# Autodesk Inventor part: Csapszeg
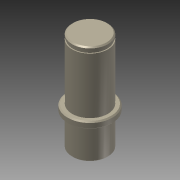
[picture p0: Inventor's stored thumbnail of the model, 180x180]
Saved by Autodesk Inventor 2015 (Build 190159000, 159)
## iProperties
Created: 2013-02
Part Number: Csapszeg
Material: Generic
Document SubType Name: Modeling
Designer: Marci
Density: 1 g/cm^3
Appearance: Light Beige
Author: Marci
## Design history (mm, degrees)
sketch "Sketch1"
  geometry: C1 r 8 at (0, 0); 1 further point
  constraints: 1 centre point, 1 coincident
  dimensions: "d0" = 16 diameter of C1
extrude "Extrusion1" new body sketch "Sketch1" distance "d1" = 14; taper "d2" = 0 deg
sketch "Sketch2"
  geometry: C1 r 8 at (0, 0) reference; C2 r 10 at (0, 0)
  constraints: 1 centre point, 1 coincident
  dimensions: "d3" = 20 diameter of C2
extrude "Extrusion2" join sketch "Sketch2" distance "d4" = 3; taper "d5" = 0 deg
sketch "Sketch3"
  geometry: C1 r 10 at (0, 0) reference; C2 r 8 at (0, 0)
  constraints: 1 centre point, 1 coincident
  dimensions: "d6" = 16 diameter of C2
extrude "Extrusion3" join sketch "Sketch3" distance "d7" = 27.5; taper "d8" = 0 deg
sketch "Sketch4"
  geometry: C1 r 8 at (0, 0) reference; C2 r 4 at (0, 0)
  constraints: 1 centre point, 1 coincident
  dimensions: "d9" = 8 diameter of C2
extrude "Extrusion4" cut sketch "Sketch4" distance "d10" = 20; taper "d11" = 0 deg
thread "Thread1" dims "d12" = 10, "d13" = 0
sketch "Sketch5"
  geometry: L1 (-8, 44.5)-(8, 44.5) reference; L2 (-8, 17)-(8, 17) reference; L3 (-8, 44.5)-(8, 44.5) reference; L4 (7.6, 42)-(7.6, 43); L5 (7.6, 43)-(9.849, 43); L6 (9.849, 43)-(9.849, 42); L7 (9.849, 42)-(7.6, 42); L8 (0, -8.9)-(0, 53.4) reference; 2 further points
  constraints: 8 end point
revolve "Revolution1" sketch "Sketch5" stored, may be unused: angle "d17" = 90 deg
chamfer "Chamfer1" distance "d18" = 0.5; stored, may be unused: second distance "d19" = 2, angle "d20" = 45 deg
chamfer "Chamfer2" distance "d21" = 0.5; stored, may be unused: second distance "d22" = 2, angle "d23" = 45 deg
chamfer "Chamfer3" distance "d24" = 0.5; stored, may be unused: second distance "d25" = 2, angle "d26" = 45 deg
chamfer "Chamfer4" distance "d27" = 0.5; stored, may be unused: second distance "d28" = 2, angle "d29" = 45 deg
body "Solid1"
node "Projected Loop1"
